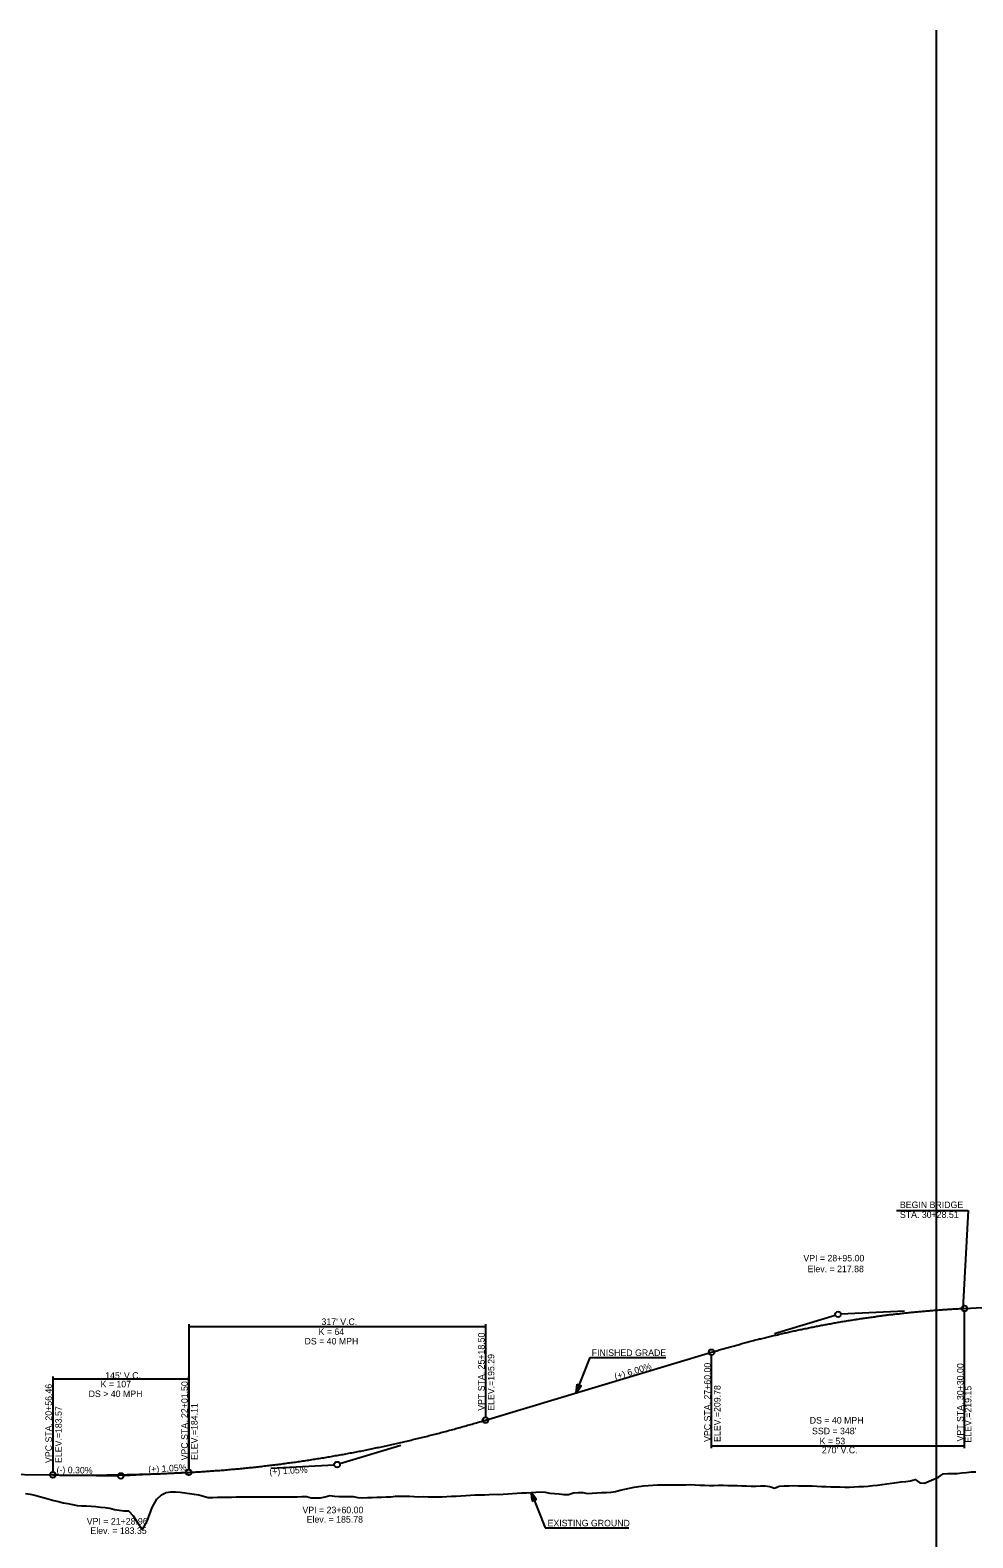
# Model space of a CAD drawing. Extents: x 69 to 2003113, y 512 to 837401.
# Drawn here: x 1924205 to 1925211, y 792764 to 794374 of the extents above; entities that cross this region are included whole.
import ezdxf

# ---------------------------------------------------------------- set-up
doc = ezdxf.new("R2010")
doc.units = 0
for name, color, linetype in [('BR_AUTO DIMENSION', 7, 'Continuous'), ('BR_CENTER LINE BASELINE', 7, 'Continuous'), ('BR_CONCRETE', 7, 'Continuous'), ('BR_GRID DOTS', 7, 'Continuous'), ('BR_GRID LINES', 7, 'Continuous'), ('BR_TEXT', 7, 'Continuous'), ('RD_PD_ALT1_TrvlWay', 7, 'Continuous'), ('RD_SHT_IplotShp', 7, 'Continuous')]:
    doc.layers.add(name, color=color, linetype=linetype)

msp = doc.modelspace()

# ---------------------------------------------------------------- linework, layer by layer
at = {"layer": 'BR_AUTO DIMENSION'}
msp.add_line((1925172.4, 791412.9), (1925172.4, 794374.1), dxfattribs=at)
at = {"layer": 'BR_CENTER LINE BASELINE'}
for p, q in [((1925138.3, 793005.6), (1925070.4, 793002.4)), ((1924999.4, 792981.9), (1925064.5, 793001.4)), ((1924600.4, 792862.2), (1924535.2, 792842.7)), ((1924230.3, 792830.7), (1924298.3, 792829.7)), ((1924372.2, 792833.4), (1924304.3, 792829.8)), ((1924461.5, 792838.1), (1924529.4, 792841.6))]:
    msp.add_line(p, q, dxfattribs=at)
for centre in [(1925067.4, 793002.3), (1924532.4, 792841.8), (1924301.3, 792829.7), (1924373.9, 792833.5)]:
    msp.add_circle(centre, 3, dxfattribs=at)
at = {"layer": 'BR_GRID DOTS'}
for p, q in [((1925129.7, 793113.3), (1925206.4, 793113.3)), ((1925200.9, 793008.6), (1925206.7, 793113.3)), ((1925202.4, 792859.3), (1925202.4, 793005.6)), ((1924373.9, 792991.8), (1924373.9, 792836.5)), ((1924373.9, 792989.3), (1924690.9, 792989.3)), ((1924690.9, 792991.8), (1924690.9, 792892.3)), ((1924932.4, 792859.3), (1924932.4, 792958.8)), ((1924228.8, 792936), (1924228.8, 792833.8)), ((1924228.8, 792933.5), (1924373.8, 792933.5)), ((1924373.8, 792936), (1924373.8, 792836.5)), ((1924932.4, 792861.8), (1925202.4, 792861.8))]:
    msp.add_line(p, q, dxfattribs=at)
for centre in [(1925202.4, 793008.6), (1924932.4, 792961.8), (1924690.9, 792889.3), (1924228.8, 792830.8), (1924373.8, 792833.5), (1924373.9, 792833.5)]:
    msp.add_circle(centre, 3, dxfattribs=at)
at = {"layer": 'BR_GRID LINES'}
for p, q in [((1925202.4, 793008.6), (1925221.4, 793009.5)), ((1924690.9, 792889.3), (1924932.4, 792961.8)), ((1924074.4, 792833.1), (1924228.8, 792830.8)), ((1924373.5, 792833.5), (1924373.9, 792833.5)), ((1924373.8, 792833.5), (1924373.9, 792833.5))]:
    msp.add_line(p, q, dxfattribs=at)
for points in [[(1924932.4, 792961.8), (1924937.8, 792963.4), (1924943.2, 792965), (1924948.6, 792966.5), (1924954, 792968.1), (1924959.4, 792969.5), (1924964.8, 792971), (1924970.2, 792972.5), (1924975.6, 792973.9), (1924981, 792975.3), (1924986.4, 792976.6), (1924991.8, 792978), (1924997.2, 792979.3), (1925002.6, 792980.5), (1925008, 792981.8), (1925013.4, 792983), (1925018.8, 792984.2), (1925024.2, 792985.4), (1925029.6, 792986.5), (1925035, 792987.6), (1925040.4, 792988.7), (1925045.8, 792989.8), (1925051.2, 792990.8), (1925056.6, 792991.8), (1925062, 792992.8), (1925067.4, 792993.8), (1925072.8, 792994.7), (1925078.2, 792995.6), (1925083.6, 792996.4), (1925089, 792997.3), (1925094.4, 792998.1), (1925099.8, 792998.9), (1925105.2, 792999.6), (1925110.6, 793000.4), (1925116, 793001.1), (1925121.4, 793001.8), (1925126.8, 793002.4), (1925132.2, 793003), (1925137.6, 793003.6), (1925143, 793004.2), (1925148.4, 793004.7), (1925153.8, 793005.2), (1925159.2, 793005.7), (1925164.6, 793006.2), (1925170, 793006.6), (1925175.4, 793007), (1925180.8, 793007.4), (1925186.2, 793007.8), (1925191.6, 793008.1), (1925197, 793008.4), (1925202.4, 793008.6)], [(1924373.9, 792833.5), (1924380.2, 792833.8), (1924386.5, 792834.2), (1924392.9, 792834.6), (1924399.2, 792835.1), (1924405.6, 792835.5), (1924411.9, 792836), (1924418.2, 792836.6), (1924424.6, 792837.1), (1924430.9, 792837.7), (1924437.3, 792838.4), (1924443.6, 792839), (1924449.9, 792839.7), (1924456.3, 792840.5), (1924462.6, 792841.2), (1924469, 792842), (1924475.3, 792842.8), (1924481.6, 792843.7), (1924488, 792844.5), (1924494.3, 792845.5), (1924500.7, 792846.4), (1924507, 792847.4), (1924513.3, 792848.4), (1924519.7, 792849.4), (1924526, 792850.5), (1924532.4, 792851.6), (1924538.7, 792852.7), (1924545, 792853.9), (1924551.4, 792855.1), (1924557.7, 792856.3), (1924564.1, 792857.6), (1924570.4, 792858.9), (1924576.7, 792860.2), (1924583.1, 792861.5), (1924589.4, 792862.9), (1924595.8, 792864.3), (1924602.1, 792865.8), (1924608.4, 792867.3), (1924614.8, 792868.8), (1924621.1, 792870.3), (1924627.5, 792871.9), (1924633.8, 792873.5), (1924640.1, 792875.1), (1924646.5, 792876.8), (1924652.8, 792878.5), (1924659.2, 792880.2), (1924665.5, 792882), (1924671.8, 792883.8), (1924678.2, 792885.6), (1924684.5, 792887.5), (1924690.9, 792889.3)], [(1924228.8, 792830.8), (1924231.7, 792830.7), (1924234.6, 792830.7), (1924237.5, 792830.6), (1924240.4, 792830.6), (1924243.3, 792830.6), (1924246.2, 792830.6), (1924249.1, 792830.6), (1924252, 792830.5), (1924254.9, 792830.5), (1924257.8, 792830.5), (1924260.7, 792830.5), (1924263.6, 792830.5), (1924266.5, 792830.5), (1924269.4, 792830.5), (1924272.3, 792830.5), (1924275.2, 792830.6), (1924278.1, 792830.6), (1924281, 792830.6), (1924283.9, 792830.6), (1924286.8, 792830.7), (1924289.7, 792830.7), (1924292.6, 792830.7), (1924295.5, 792830.8), (1924298.4, 792830.8), (1924301.3, 792830.9), (1924304.2, 792831), (1924307.1, 792831), (1924310, 792831.1), (1924312.9, 792831.1), (1924315.8, 792831.2), (1924318.7, 792831.3), (1924321.6, 792831.4), (1924324.5, 792831.5), (1924327.4, 792831.5), (1924330.3, 792831.6), (1924333.2, 792831.7), (1924336.1, 792831.8), (1924339, 792831.9), (1924341.9, 792832), (1924344.8, 792832.1), (1924347.7, 792832.3), (1924350.6, 792832.4), (1924353.5, 792832.5), (1924356.4, 792832.6), (1924359.3, 792832.8), (1924362.2, 792832.9), (1924365.1, 792833), (1924368, 792833.2), (1924370.9, 792833.3), (1924373.8, 792833.5)]]:
    msp.add_spline(points, degree=3, dxfattribs=at)
at = {"layer": 'BR_TEXT'}
for points in [[(1924924.7, 792819.7), (1924929.7, 792819.5), (1924934.7, 792819.6), (1924939.7, 792819.8), (1924944.7, 792819.7), (1924949.7, 792819.6), (1924954.7, 792819.5), (1924959.7, 792819.3), (1924964.7, 792819.2), (1924969.7, 792819.1), (1924974.7, 792818.9), (1924979.7, 792818.9), (1924984.7, 792819.1), (1924989.7, 792819.2), (1924994.7, 792818.4), (1924999.7, 792816.5), (1925004.7, 792818.8), (1925009.7, 792819), (1925014.7, 792819.1), (1925019.7, 792819.3), (1925024.7, 792819.2), (1925029.7, 792819), (1925034.7, 792819), (1925039.7, 792819), (1925044.7, 792818.7), (1925049.7, 792818.4), (1925054.7, 792818.3), (1925059.7, 792818.2), (1925064.7, 792818.1), (1925069.7, 792817.9), (1925074.7, 792817.5), (1925079.7, 792817.7), (1925084.7, 792818), (1925089.7, 792818.3), (1925094.7, 792818.4), (1925099.7, 792818.8), (1925104.7, 792819.3), (1925109.7, 792819.9), (1925114.7, 792820.6), (1925119.7, 792821.2), (1925124.7, 792821.8), (1925129.7, 792822.5), (1925134.7, 792823.2), (1925139.7, 792823.8), (1925144.7, 792824.6), (1925149.7, 792825.7), (1925154.7, 792822.3), (1925159.7, 792821.9), (1925164.7, 792823.9), (1925169.7, 792826.1), (1925174.7, 792828.4), (1925179.7, 792832), (1925184.7, 792832.1), (1925189.7, 792832.1), (1925194.7, 792832.3), (1925199.7, 792832.9), (1925204.7, 792833.5), (1925209.7, 792834.1), (1925214.7, 792834.2)], [(1924199.7, 792811), (1924204.7, 792810.3), (1924209.7, 792809.2), (1924214.7, 792807.7), (1924219.7, 792806.3), (1924224.7, 792804.9), (1924229.7, 792803.5), (1924234.7, 792802.2), (1924239.7, 792801.1), (1924244.7, 792800.1), (1924249.7, 792799.1), (1924254.7, 792798), (1924259.7, 792797.8), (1924264.7, 792797.7), (1924269.7, 792797.4), (1924274.7, 792796.9), (1924279.7, 792796.4), (1924284.7, 792795.9), (1924289.7, 792795.1), (1924294.7, 792793.7), (1924299.7, 792793.2), (1924304.7, 792792.3), (1924309.7, 792792.3), (1924314.7, 792787), (1924319.7, 792779.2), (1924324.7, 792772.3), (1924329.7, 792781.5), (1924334.7, 792795.8), (1924339.7, 792805), (1924344.7, 792809.4), (1924349.7, 792812.1), (1924354.7, 792812.8), (1924359.7, 792812.7), (1924364.7, 792812.4), (1924369.7, 792811.7), (1924374.7, 792810.9), (1924379.7, 792810.1), (1924384.7, 792809.3), (1924389.7, 792808.1), (1924394.7, 792806.7), (1924399.7, 792806.7), (1924404.7, 792806.9), (1924409.7, 792806.9), (1924414.7, 792807), (1924419.7, 792807.1), (1924424.7, 792807.3)], [(1924424.7, 792807.3), (1924429.7, 792807.4), (1924434.7, 792807.4), (1924439.7, 792807.4), (1924444.7, 792807.4), (1924449.7, 792807.3), (1924454.7, 792807.2), (1924459.7, 792807.2), (1924464.7, 792807.2), (1924469.7, 792807.2), (1924474.7, 792807.3), (1924479.7, 792807.3), (1924484.7, 792807.4), (1924489.7, 792807.5), (1924494.7, 792807.6), (1924499.7, 792807.7), (1924504.7, 792806.3), (1924509.7, 792806.2), (1924514.7, 792806.1), (1924519.7, 792807.4), (1924524.7, 792808.6), (1924529.7, 792808.2), (1924534.7, 792807.7), (1924539.7, 792807.6), (1924544.7, 792807.6), (1924549.7, 792807.8), (1924554.7, 792806.8), (1924559.7, 792806.3), (1924564.7, 792806.6), (1924569.7, 792806.8), (1924574.7, 792807), (1924579.7, 792807.1), (1924584.7, 792807.2), (1924589.7, 792807.5), (1924594.7, 792808.2), (1924599.7, 792808.2), (1924604.7, 792808.1), (1924609.7, 792808), (1924614.7, 792807.6), (1924619.7, 792807.5), (1924624.7, 792807.6), (1924629.7, 792807.5), (1924634.7, 792807.5), (1924639.7, 792807.5), (1924644.7, 792807.5), (1924649.7, 792807.6), (1924654.7, 792807.9), (1924659.7, 792808.2), (1924664.7, 792808.4), (1924669.7, 792808.7), (1924674.7, 792809), (1924679.7, 792809.3), (1924684.7, 792809.4), (1924689.7, 792809.6), (1924694.7, 792809.8), (1924699.7, 792810.1), (1924704.7, 792810), (1924709.7, 792810.3), (1924714.7, 792810.6), (1924719.7, 792810.9), (1924724.7, 792811.1), (1924729.7, 792811.5), (1924734.7, 792811.7), (1924739.7, 792812), (1924744.7, 792812.3), (1924749.7, 792812.6), (1924754.7, 792812.2), (1924759.7, 792811.2), (1924764.7, 792810.8), (1924769.7, 792810.4), (1924774.7, 792810), (1924779.7, 792810), (1924784.7, 792811.6), (1924789.7, 792811.8), (1924794.7, 792812), (1924799.7, 792811), (1924804.7, 792811.3), (1924809.7, 792811.6), (1924814.7, 792811.8), (1924819.7, 792812.1), (1924824.7, 792812.3), (1924829.7, 792813.2), (1924834.7, 792814.3), (1924839.7, 792815.4), (1924844.7, 792816.5), (1924849.7, 792817.5), (1924854.7, 792818.5), (1924859.7, 792819), (1924864.7, 792819.5), (1924869.7, 792819.9), (1924874.7, 792820.3), (1924879.7, 792820.3), (1924884.7, 792820.3), (1924889.7, 792820.3), (1924894.7, 792820.3), (1924899.7, 792820.2), (1924904.7, 792820.2), (1924909.7, 792820.4), (1924914.7, 792820.2), (1924919.7, 792819.9), (1924924.7, 792819.7)]]:
    msp.add_lwpolyline(points, dxfattribs=at)
at = {"layer": 'RD_PD_ALT1_TrvlWay'}
for p, q in [((1924787.7, 792918.4), (1924802.7, 792956.3)), ((1924802.7, 792956.3), (1924883.4, 792956.3)), ((1924787.7, 792918.4), (1924788.9, 792927.6)), ((1924787.7, 792918.4), (1924788.9, 792927.6)), ((1924791, 792926.8), (1924787.7, 792918.4)), ((1924791, 792926.8), (1924787.7, 792918.4)), ((1924787.7, 792918.4), (1924793.1, 792925.9)), ((1924787.7, 792918.4), (1924793.1, 792925.9)), ((1924788.9, 792927.6), (1924793.1, 792925.9)), ((1924788.9, 792927.6), (1924793.1, 792925.9)), ((1924739.7, 792812), (1924754.7, 792774.1)), ((1924743, 792803.6), (1924739.7, 792812)), ((1924739.7, 792812), (1924745.1, 792804.5)), ((1924739.7, 792812), (1924740.9, 792802.8)), ((1924740.9, 792802.8), (1924745.1, 792804.5)), ((1924754.7, 792774.1), (1924843.9, 792774.1))]:
    msp.add_line(p, q, dxfattribs=at)
for points in [[(1924790.9, 792926.7), (1924787.8, 792918.9), (1924790.9, 792926.8), (1924787.9, 792919.3), (1924790.8, 792926.8), (1924787.9, 792919.5), (1924790.7, 792926.8), (1924788, 792919.9), (1924790.6, 792926.8), (1924788, 792920.4), (1924790.5, 792926.9), (1924788.1, 792920.9), (1924790.3, 792926.9), (1924788.2, 792921.3), (1924790.3, 792927), (1924788.2, 792921.7), (1924790.2, 792926.9), (1924788.3, 792922.1), (1924790.1, 792927), (1924788.3, 792922.5), (1924790, 792927.1), (1924788.4, 792923), (1924789.9, 792927.1), (1924788.5, 792923.6), (1924789.8, 792927.2), (1924788.5, 792924), (1924789.7, 792927.2), (1924788.6, 792924.6), (1924789.5, 792927.2), (1924788.7, 792925.1), (1924789.4, 792927.3), (1924788.7, 792925.6), (1924789.3, 792927.3), (1924788.8, 792926), (1924789.3, 792927.4), (1924788.9, 792926.5), (1924789.1, 792927.4), (1924788.9, 792927), (1924789, 792927.4)], [(1924790.9, 792926.7), (1924787.8, 792918.9), (1924790.9, 792926.8), (1924787.9, 792919.3), (1924790.8, 792926.8), (1924787.9, 792919.5), (1924790.7, 792926.8), (1924788, 792919.9), (1924790.6, 792926.8), (1924788, 792920.4), (1924790.5, 792926.9), (1924788.1, 792920.9), (1924790.3, 792926.9), (1924788.2, 792921.3), (1924790.3, 792927), (1924788.2, 792921.7), (1924790.2, 792926.9), (1924788.3, 792922.1), (1924790.1, 792927), (1924788.3, 792922.5), (1924790, 792927.1), (1924788.4, 792923), (1924789.9, 792927.1), (1924788.5, 792923.6), (1924789.8, 792927.2), (1924788.5, 792924), (1924789.7, 792927.2), (1924788.6, 792924.6), (1924789.5, 792927.2), (1924788.7, 792925.1), (1924789.4, 792927.3), (1924788.7, 792925.6), (1924789.3, 792927.3), (1924788.8, 792926), (1924789.3, 792927.4), (1924788.9, 792926.5), (1924789.1, 792927.4), (1924788.9, 792927), (1924789, 792927.4)], [(1924788, 792918.9), (1924791, 792926.6), (1924788.1, 792919.2), (1924791.1, 792926.6), (1924788.3, 792919.4), (1924791.2, 792926.6), (1924788.5, 792919.6), (1924791.3, 792926.6), (1924788.7, 792919.9), (1924791.4, 792926.5), (1924788.9, 792920.1), (1924791.4, 792926.5), (1924789.1, 792920.4), (1924791.5, 792926.5), (1924789.3, 792920.8), (1924791.6, 792926.4), (1924789.5, 792921.1), (1924791.7, 792926.4), (1924789.7, 792921.4), (1924791.8, 792926.4), (1924790, 792921.7), (1924791.9, 792926.4), (1924790.2, 792922.1), (1924791.9, 792926.3), (1924790.5, 792922.5), (1924792, 792926.3), (1924790.8, 792922.8), (1924792.1, 792926.3), (1924791.1, 792923.2), (1924792.2, 792926.2), (1924791.3, 792923.6), (1924792.3, 792926.2), (1924791.5, 792923.9), (1924792.4, 792926.1), (1924791.8, 792924.2), (1924792.4, 792926), (1924792.1, 792924.7), (1924792.6, 792926.1), (1924792.3, 792924.9), (1924792.7, 792926), (1924792.4, 792925.1), (1924792.8, 792925.9), (1924793, 792925.9), (1924792.8, 792925.9)], [(1924788, 792918.9), (1924791, 792926.6), (1924788.1, 792919.2), (1924791.1, 792926.6), (1924788.3, 792919.4), (1924791.2, 792926.6), (1924788.5, 792919.6), (1924791.3, 792926.6), (1924788.7, 792919.9), (1924791.4, 792926.5), (1924788.9, 792920.1), (1924791.4, 792926.5), (1924789.1, 792920.4), (1924791.5, 792926.5), (1924789.3, 792920.8), (1924791.6, 792926.4), (1924789.5, 792921.1), (1924791.7, 792926.4), (1924789.7, 792921.4), (1924791.8, 792926.4), (1924790, 792921.7), (1924791.9, 792926.4), (1924790.2, 792922.1), (1924791.9, 792926.3), (1924790.5, 792922.5), (1924792, 792926.3), (1924790.8, 792922.8), (1924792.1, 792926.3), (1924791.1, 792923.2), (1924792.2, 792926.2), (1924791.3, 792923.6), (1924792.3, 792926.2), (1924791.5, 792923.9), (1924792.4, 792926.1), (1924791.8, 792924.2), (1924792.4, 792926), (1924792.1, 792924.7), (1924792.6, 792926.1), (1924792.3, 792924.9), (1924792.7, 792926), (1924792.4, 792925.1), (1924792.8, 792925.9), (1924793, 792925.9), (1924792.8, 792925.9)], [(1924742.9, 792803.7), (1924739.9, 792811.5), (1924742.9, 792803.7), (1924739.9, 792811.1), (1924742.8, 792803.7), (1924740, 792810.9), (1924742.7, 792803.6), (1924740, 792810.5), (1924742.6, 792803.6), (1924740.1, 792810), (1924742.5, 792803.5), (1924740.2, 792809.5), (1924742.4, 792803.5), (1924740.2, 792809.1), (1924742.3, 792803.5), (1924740.3, 792808.7), (1924742.2, 792803.5), (1924740.3, 792808.3), (1924742.1, 792803.4), (1924740.4, 792807.9), (1924742, 792803.4), (1924740.4, 792807.4), (1924741.9, 792803.3), (1924740.5, 792806.8), (1924741.8, 792803.2), (1924740.5, 792806.4), (1924741.7, 792803.2), (1924740.6, 792805.8), (1924741.6, 792803.2), (1924740.7, 792805.3), (1924741.5, 792803.1), (1924740.8, 792804.8), (1924741.4, 792803.1), (1924740.8, 792804.4), (1924741.3, 792803), (1924740.9, 792803.9), (1924741.2, 792803), (1924741, 792803.4), (1924741.1, 792803)], [(1924740, 792811.5), (1924743.1, 792803.8), (1924740.2, 792811.2), (1924743.2, 792803.8), (1924740.3, 792811), (1924743.2, 792803.8), (1924740.5, 792810.8), (1924743.3, 792803.8), (1924740.7, 792810.5), (1924743.4, 792803.9), (1924740.9, 792810.3), (1924743.5, 792803.9), (1924741.1, 792810), (1924743.6, 792803.9), (1924741.4, 792809.6), (1924743.7, 792804), (1924741.6, 792809.3), (1924743.8, 792804), (1924741.8, 792809), (1924743.8, 792804), (1924742, 792808.7), (1924743.9, 792804.1), (1924742.3, 792808.3), (1924744, 792804.1), (1924742.6, 792807.9), (1924744.1, 792804.1), (1924742.8, 792807.6), (1924744.2, 792804.1), (1924743.1, 792807.2), (1924744.2, 792804.2), (1924743.3, 792806.8), (1924744.3, 792804.3), (1924743.6, 792806.5), (1924744.4, 792804.3), (1924743.8, 792806.2), (1924744.5, 792804.4), (1924744.1, 792805.7), (1924744.6, 792804.4), (1924744.3, 792805.5), (1924744.8, 792804.4), (1924744.5, 792805.3), (1924744.9, 792804.5), (1924745, 792804.5), (1924744.8, 792804.5)]]:
    msp.add_lwpolyline(points, dxfattribs=at)

# ---------------------------------------------------------------- texts
at = {"layer": 'BR_CENTER LINE BASELINE'}
for s, rotation, p in [('(+) 6.00%', 16.6992, (1924829.8, 792932.2)), ('(+) 1.05%', 3.0026, (1924330.9, 792833.2)), ('(-) 0.30%', 359.1406, (1924232.7, 792832.7)), ('(+) 1.05%', 3.0025, (1924460.2, 792830.8))]:
    msp.add_text(s, height=7, rotation=rotation, dxfattribs=at).set_placement(p)
at = {"layer": 'BR_CONCRETE'}
for s, p in [('VPT STA. 25+18.50 ', (1924689.9, 792899.3)), ('ELEV.=195.29', (1924700.4, 792899.3)), ('VPC STA. 27+60.00 ', (1924931.4, 792866)), ('VPT STA. 30+30.00 ', (1925201.4, 792866.5)), ('VPC STA. 20+56.46 ', (1924227.8, 792843.5)), ('VPC STA. 22+01.50 ', (1924372.9, 792846.3)), ('ELEV.=209.78', (1924941.9, 792866)), ('ELEV.=219.15', (1925209.9, 792865.3)), ('ELEV.=184.11', (1924383.4, 792846.7)), ('ELEV.=183.57', (1924238.3, 792843.5))]:
    msp.add_text(s, height=7, rotation=90, dxfattribs=at).set_placement(p)
at = {"layer": 'BR_GRID DOTS'}
for s, p in [('K = 64', (1924512.6, 792980.2)), ("317' V.C.", (1924515.7, 792990.9)), ('DS = 40 MPH', (1924497.6, 792970.1)), ("145' V.C.", (1924284.7, 792933.5)), ('K = 107', (1924279.8, 792924.3)), ('DS > 40 MPH', (1924267, 792913.9)), ('DS = 40 MPH', (1925037.2, 792885.6)), ("SSD = 348'", (1925039.6, 792874.2)), ('K = 53', (1925047.7, 792863.4)), ("270' V.C.", (1925050.1, 792853.9))]:
    msp.add_text(s, height=7, dxfattribs=at).set_placement(p)
at = {"layer": 'RD_PD_ALT1_TrvlWay'}
for s, p in [('FINISHED GRADE', (1924804.3, 792957.8)), ('EXISTING GROUND', (1924757.2, 792775.8))]:
    msp.add_text(s, height=7, dxfattribs=at).set_placement(p)
at = {"layer": 'RD_SHT_IplotShp'}
for s, p in [('BEGIN BRIDGE', (1925133.5, 793115.8)), ('STA. 30+28.51', (1925133.5, 793105.3)), ('VPI = 28+95.00', (1925030.4, 793058.8)), ('Elev. = 217.88', (1925034.9, 793047.3)), ('VPI = 23+60.00', (1924495.4, 792789.8)), ('VPI = 21+28.96', (1924265, 792777.7)), ('Elev. = 185.78', (1924499.9, 792779.8)), ('Elev. = 183.35', (1924268.9, 792767.7))]:
    msp.add_text(s, height=7, dxfattribs=at).set_placement(p)

doc.saveas('drawing.dxf')
